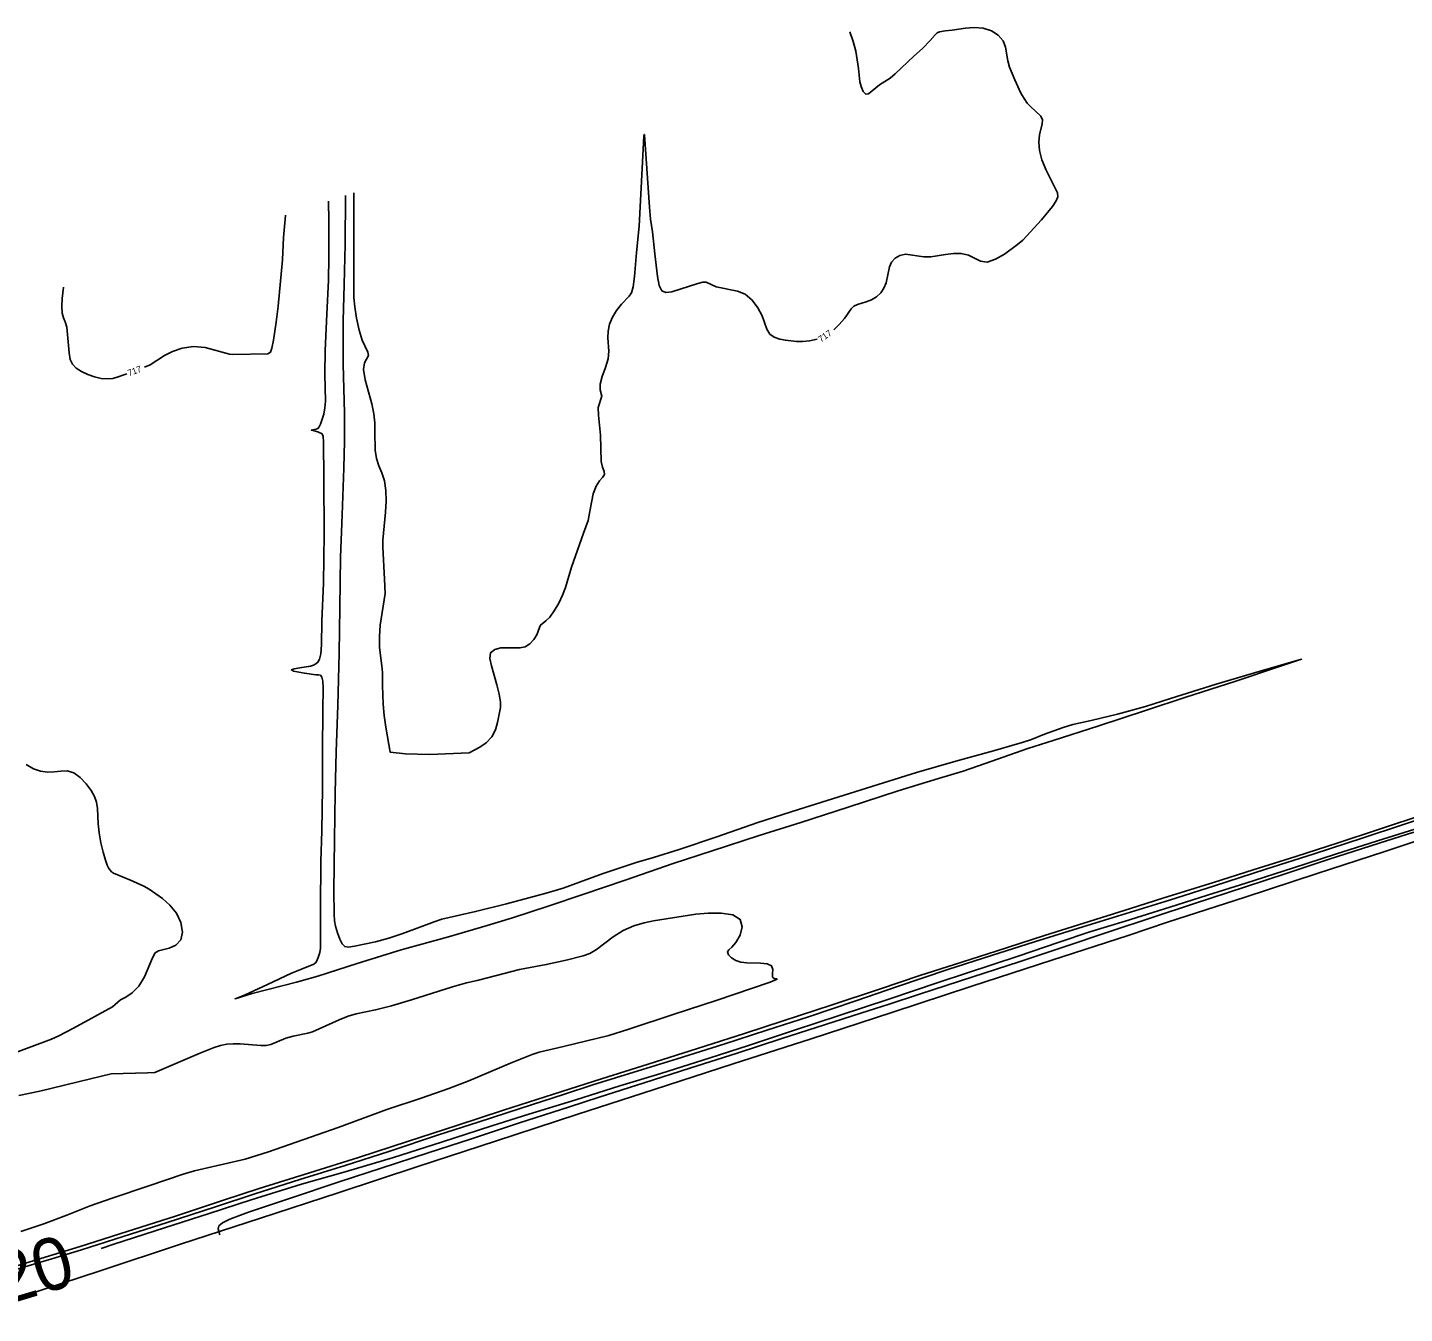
# Model space of a CAD drawing. Extents: x -361782338 to 28259792, y -263199453 to 8342113.
# Drawn here: x 1406946 to 1407815, y 577421 to 578233 of the extents above; entities that cross this region are included whole.
import ezdxf

# ---------------------------------------------------------------- set-up
doc = ezdxf.new("R2010")
doc.units = 0
for name, color, linetype in [('DT_X_Contour_Minor', 7, 'Continuous'), ('Level 14', 7, 'Continuous'), ('Level 19', 7, 'Continuous')]:
    doc.layers.add(name, color=color, linetype=linetype)

msp = doc.modelspace()

# ---------------------------------------------------------------- linework, layer by layer
at = {"layer": 'DT_X_Contour_Minor'}
for points in [[(1407465.01, 578230.1), (1407467.24, 578223.89), (1407468.75, 578217.77), (1407470.43, 578206.82), (1407471.33, 578198.54), (1407472.25, 578195.43), (1407473.56, 578192.44), (1407475.09, 578190.64), (1407476.74, 578190.8), (1407483.85, 578196.54), (1407490.46, 578200.85), (1407493.71, 578203.6), (1407505.45, 578214.64), (1407510.96, 578219.61), (1407515.74, 578224.5), (1407518.82, 578228.2), (1407520.15, 578229.38), (1407521.65, 578230.08), (1407525.14, 578230.58), (1407529.65, 578231.02), (1407537.95, 578232.27), (1407543.52, 578232.76), (1407549.22, 578232.39), (1407554.44, 578230.72), (1407558.77, 578227.92), (1407561.81, 578224.32), (1407563.39, 578220.26), (1407564.68, 578211.72), (1407565.78, 578207.66), (1407569.17, 578199.65), (1407573.04, 578191.42), (1407575.02, 578187.88), (1407577.02, 578185.1), (1407579.09, 578182.89), (1407585.52, 578176.86), (1407586.59, 578174.54), (1407586.47, 578171.89), (1407584.72, 578164.99), (1407584.36, 578160.42), (1407584.84, 578155.12), (1407586.33, 578149.17), (1407588.88, 578142.79), (1407596.04, 578128.33), (1407596.35, 578125.87), (1407595.32, 578123.27), (1407592.95, 578119.78), (1407586.02, 578111.36), (1407574.24, 578098.51), (1407570.86, 578095.77), (1407562.62, 578089.76), (1407557.09, 578086.47), (1407551.82, 578084.64), (1407547.51, 578085.16), (1407539.85, 578089.09), (1407535.35, 578090.07), (1407530.43, 578090.11), (1407525.43, 578089.55), (1407516.13, 578088.06), (1407511.85, 578087.91), (1407500.18, 578089.57), (1407496.64, 578088.83), (1407493.57, 578087.12), (1407491.31, 578084.69), (1407490.07, 578081.74), (1407488.03, 578071.48), (1407486.59, 578068.15), (1407484.52, 578065.18), (1407481.77, 578062.71), (1407478.62, 578060.81), (1407475.41, 578059.48), (1407469.79, 578057.97), (1407467.6, 578056.89), (1407465.83, 578055.04), (1407461.71, 578049.07), (1407458.4, 578045.19), (1407454.89, 578041.92)], [(1407444.39, 578036.01), (1407439.66, 578034.96), (1407435.16, 578034.53), (1407431.32, 578034.49), (1407424.43, 578035.26), (1407420.77, 578036), (1407417.27, 578037.23), (1407414.46, 578039.24), (1407412.68, 578042.25), (1407409.68, 578050.8), (1407407.04, 578055.86), (1407403.44, 578060.64), (1407399.03, 578064.32), (1407394.05, 578066.36), (1407380.71, 578069.08), (1407374.29, 578072.01), (1407372.35, 578071.93), (1407369.14, 578071.07), (1407352.77, 578065.96), (1407348.9, 578065.43), (1407346.39, 578066.52), (1407344.75, 578069.84), (1407343.56, 578075.65), (1407342, 578089.87), (1407340.5, 578103.77), (1407339.31, 578111.73), (1407338.57, 578119.36), (1407336.94, 578143.8), (1407335.49, 578165.04), (1407335.24, 578165.3), (1407335.03, 578164.08), (1407334.03, 578143.7), (1407332.01, 578107.29), (1407330.35, 578090.66), (1407329.05, 578075.48), (1407328.22, 578069.13), (1407327.19, 578065.29), (1407325.76, 578063.04), (1407320.87, 578057.99), (1407317.82, 578054.17), (1407315.17, 578049.89), (1407313.41, 578045.48), (1407312.52, 578041.1), (1407312.35, 578036.84), (1407312.89, 578028.43), (1407312.39, 578023.58), (1407310.78, 578018), (1407308.8, 578012.35), (1407307.45, 578007.49), (1407307.42, 578004.07), (1407308.44, 578000.09), (1407306.14, 577992.87), (1407306.35, 577987.92), (1407307.7, 577975.38), (1407308.02, 577958.64), (1407308.94, 577955.07), (1407309.91, 577952.45), (1407310.11, 577950.46), (1407308.98, 577948.71), (1407306.98, 577946.53), (1407304.83, 577943.19), (1407303.11, 577938.3), (1407301.13, 577928.42), (1407299.81, 577921.59), (1407297.02, 577913.5), (1407289.45, 577892.03), (1407285.59, 577879.14), (1407283.75, 577874.34), (1407281.27, 577869.24), (1407278.43, 577864.4), (1407275.62, 577860.53), (1407273.18, 577858.11), (1407269.88, 577855.43), (1407269.11, 577853.86), (1407267.45, 577849.29), (1407265.62, 577846.4), (1407263.08, 577843.67), (1407260.09, 577841.72), (1407256.82, 577840.98), (1407244.84, 577841.07), (1407240.9, 577840.07), (1407238.32, 577837.93), (1407237.78, 577834.41), (1407238.77, 577829.68), (1407242.31, 577817.82), (1407243.77, 577811.81), (1407244.61, 577806.84), (1407244.63, 577803.44), (1407242.56, 577793.93), (1407241.34, 577789.31), (1407239.09, 577784.82), (1407235.51, 577781.1), (1407231.45, 577778.29), (1407224.81, 577774.81), (1407200, 577773.74), (1407184.66, 577774.24), (1407174.9, 577775.11), (1407172.14, 577790.97), (1407171.14, 577798.37), (1407170.48, 577805.48), (1407170.04, 577817.31)], [(1407135.98, 578123.16), (1407136.07, 578110.73), (1407136.27, 578087.48), (1407136.02, 578073.19), (1407134.99, 578051.77), (1407133.89, 578028.9), (1407133.73, 578013.85), (1407133.98, 577996.9), (1407133.67, 577992.59), (1407132.91, 577988.54), (1407130.89, 577982.22), (1407130.07, 577980.53), (1407129.27, 577979.65), (1407128.25, 577979.24), (1407125.1, 577978.61), (1407126.91, 577978.14), (1407129.21, 577977.43), (1407130.49, 577976.83), (1407131.22, 577976.69), (1407131.95, 577976.13), (1407132.53, 577974.5), (1407132.83, 577971.21), (1407133.04, 577948.18), (1407133.2, 577913.17), (1407132.79, 577881.91), (1407131.67, 577857.9), (1407131.47, 577842.97), (1407131.13, 577837.37), (1407130.36, 577833.87), (1407129.24, 577831.99), (1407127.93, 577830.98), (1407126.47, 577830.24), (1407124.54, 577829.58), (1407117.85, 577828.39), (1407114.25, 577827.78), (1407112.52, 577827.13), (1407113.76, 577826.43), (1407120.71, 577825.08), (1407127.89, 577824.05), (1407129.48, 577824.06), (1407130.81, 577823.77), (1407131.78, 577822.61), (1407132.35, 577820.08), (1407132.59, 577815.87), (1407132.47, 577801.65), (1407132.12, 577776.32), (1407132.13, 577752.26), (1407131.67, 577725.61), (1407131.15, 577706.24), (1407130.89, 577676.89), (1407130.83, 577651.52), (1407130.51, 577648.77), (1407129.45, 577645.46), (1407128.23, 577642.5), (1407126.66, 577641.37), (1407118.83, 577638.14), (1407112.56, 577635.56), (1407097.47, 577628.58), (1407083.37, 577622), (1407076.96, 577619.52), (1407087.68, 577622.76), (1407115.72, 577629.87), (1407129.23, 577633.84), (1407153.96, 577641.72), (1407181.86, 577650.35), (1407211.7, 577658.55), (1407236.15, 577665.78), (1407252, 577670.51), (1407274.62, 577677.95), (1407297.19, 577685.61), (1407323.31, 577694.45), (1407353.45, 577704.82), (1407378.14, 577712.98), (1407407.78, 577722.55), (1407434.11, 577730.86), (1407463.92, 577740.37), (1407495.61, 577750.75), (1407520.96, 577758.48), (1407536.65, 577763.3), (1407550.55, 577768), (1407577.47, 577777.47), (1407593.42, 577782.67), (1407622.22, 577791.82), (1407651.58, 577801.55), (1407677.13, 577809.91), (1407708.01, 577819.89), (1407735.71, 577829.01), (1407750.18, 577833.9), (1407724.02, 577826.3), (1407696.22, 577818.2), (1407667.43, 577809.05), (1407651.68, 577804.14), (1407633.92, 577799.21), (1407617.47, 577795.28), (1407605.83, 577792.7), (1407599.61, 577790.8), (1407587.96, 577786.51), (1407579.67, 577783.17), (1407573.92, 577781.28), (1407555.66, 577776.15), (1407531.88, 577769.53)], [(1407531.88, 577769.53), (1407507.22, 577762.28), (1407486.25, 577755.88), (1407461.55, 577748.04), (1407432.64, 577739.03), (1407406.87, 577730.79), (1407381.17, 577721.76), (1407357.39, 577713.81), (1407341.21, 577708.66), (1407330.24, 577705.6), (1407309.35, 577698.67), (1407294.33, 577693.2), (1407284.04, 577689.32), (1407273.46, 577686.19), (1407248.22, 577679.36), (1407228.81, 577674.58), (1407207.56, 577669.66), (1407202.58, 577668.13), (1407190.25, 577663.48), (1407182.34, 577660.49), (1407173.96, 577657.68), (1407165.71, 577655.46), (1407152.43, 577652.74), (1407148.58, 577652.17), (1407146.21, 577652.48), (1407144.56, 577654.09), (1407143.01, 577657.21), (1407141.58, 577661.2), (1407140.45, 577665.23), (1407139.77, 577668.8), (1407139.44, 577672.9), (1407139.37, 577687.56), (1407139.78, 577720.09), (1407140.18, 577749.51), (1407140.77, 577775.33), (1407141.82, 577804.72), (1407142.66, 577837.74), (1407143.07, 577866.56), (1407143.53, 577898.4), (1407144.5, 577925.04), (1407145.68, 577954.49), (1407146.03, 577971.56), (1407146.03, 577989.3), (1407145.14, 578020.24), (1407145.21, 578047.57), (1407145.87, 578070.46), (1407146.49, 578095.84), (1407146.59, 578126.61)], [(1407170.04, 577817.31), (1407169.97, 577825.48), (1407169.63, 577829.72), (1407168.25, 577841.25), (1407168.05, 577848.17), (1407168.66, 577855.41), (1407171.74, 577875.31), (1407171.41, 577884.43), (1407170.16, 577904.75), (1407170.32, 577909.01), (1407172.03, 577926.72), (1407172.33, 577933.7), (1407172.15, 577940.52), (1407171.28, 577946.59), (1407169.67, 577951.54), (1407167.79, 577955.93), (1407166.22, 577960.55), (1407165.43, 577965.97), (1407165.24, 577977.74), (1407165.16, 577983.22), (1407164.66, 577988.82), (1407163.4, 577995.2), (1407159.2, 578010.37), (1407158.13, 578016.79), (1407158.75, 578021.03), (1407161.18, 578025.59), (1407160.77, 578027.74), (1407157.27, 578035.35), (1407155.34, 578041.76), (1407153.73, 578049.16), (1407152.59, 578056.35), (1407152.04, 578062.34), (1407151.95, 578070.08), (1407152.03, 578080.09), (1407152.04, 578109.63), (1407151.88, 578128.33)], [(1407108.81, 578114.33), (1407108.79, 578114.13), (1407107.47, 578100.11), (1407106.9, 578086.15), (1407104.24, 578056.85), (1407102.99, 578046.73), (1407101.22, 578035.29), (1407100.28, 578030.35), (1407099.34, 578027.68), (1407097.74, 578026.76), (1407075.66, 578026.22), (1407073.39, 578026.47), (1407058.09, 578030.7), (1407050.68, 578031.37), (1407043.62, 578030.36), (1407037.42, 578028.2), (1407032.48, 578025.66), (1407023.31, 578019.78), (1407019.82, 578018.31)], [(1407008.56, 578014.14), (1407006.84, 578013.5), (1407003.26, 578012.14), (1406999.77, 578011.2), (1406996.17, 578010.88), (1406992.37, 578011.19), (1406988.34, 578012.12), (1406984.11, 578013.61), (1406980.09, 578015.54), (1406976.74, 578017.74), (1406974.42, 578020.17), (1406972.99, 578023.22), (1406972.2, 578027.36), (1406970.82, 578043.59), (1406969.79, 578046.95), (1406968.63, 578049.5), (1406967.77, 578052.48), (1406967.53, 578056.73), (1406967.8, 578061.67), (1406968.75, 578068.81)], [(1406931.28, 577582.91), (1406961.05, 577593.95), (1406965.77, 577596.09), (1406975.08, 577600.91), (1406999.61, 577614.3), (1407004.66, 577618.78), (1407007.98, 577620.55), (1407012.13, 577623.2), (1407016.29, 577627.39), (1407019.79, 577633.37), (1407024.79, 577645.31), (1407026.59, 577648.42), (1407028.56, 577649.82), (1407035.37, 577651.51), (1407039.59, 577653.38), (1407042.74, 577656.66), (1407043.8, 577661.64), (1407042.8, 577667.58), (1407040.03, 577673.53), (1407035.9, 577678.66), (1407031.13, 577682.85), (1407022.78, 577688.62), (1407019.35, 577690.6), (1407011.06, 577694.36), (1407000.18, 577698.87), (1406998.9, 577699.68), (1406997.32, 577701.72), (1406996.35, 577703.75), (1406995.14, 577707.1), (1406993.68, 577712.04), (1406992.24, 577718), (1406991.16, 577724.21), (1406990.64, 577730.01), (1406990.21, 577739.73), (1406989.56, 577743.61), (1406988.28, 577747.21), (1406986.14, 577751.02), (1406983.03, 577755.28), (1406979.23, 577759.31), (1406975.12, 577762.2), (1406971.01, 577763.32), (1406966.92, 577763.21), (1406962.8, 577762.71), (1406958.57, 577762.55), (1406954.22, 577763.11), (1406949.7, 577764.67), (1406945.02, 577767.43)], [(1407838.58, 577737.44), (1407813.86, 577729.31), (1407788.46, 577720.85), (1407758.17, 577710.96), (1407727.68, 577701.27), (1407695.22, 577690.89), (1407666.84, 577681.75), (1407636.78, 577672.52), (1407612.1, 577664.91), (1407581.56, 577655.39), (1407554.55, 577646.85), (1407526.81, 577638.06), (1407495.18, 577627.19), (1407468.88, 577618.21), (1407439.01, 577608.18), (1407412.68, 577599.56), (1407385.54, 577590.77), (1407355.99, 577581.56), (1407331.51, 577573.94), (1407302.89, 577565.1), (1407284.89, 577559.34), (1407256.89, 577550.18), (1407230.48, 577541.63), (1407205.49, 577533.48), (1407174.14, 577523.14), (1407146.51, 577514.27), (1407117.89, 577505.31), (1407089.38, 577496.26), (1407064.62, 577488.19), (1407034.13, 577478.27), (1407006.29, 577469.48), (1406979.95, 577461.05), (1406961.37, 577455.32), (1406935.08, 577447.53)], [(1407642.25, 577676.49), (1407662.7, 577682.97), (1407694.65, 577692.99), (1407719.69, 577700.97), (1407746.53, 577709.42), (1407773.37, 577718.01), (1407798.78, 577726.34), (1407828.57, 577736.31)], [(1406992.43, 577461.87), (1407000.49, 577464.47), (1407032.36, 577474.87), (1407060.68, 577483.93), (1407087.17, 577492.48), (1407118.95, 577502.52), (1407146.43, 577510.28), (1407177.01, 577519.27), (1407207.26, 577528.98), (1407239.07, 577539.31), (1407262.39, 577546.62), (1407292, 577555.77), (1407319.92, 577564.45), (1407345.79, 577572.37), (1407376.87, 577582.18), (1407401.02, 577590.05), (1407430.21, 577599.69), (1407458.22, 577608.85), (1407489.57, 577619.21), (1407520.72, 577629.71), (1407538.64, 577635.6), (1407571.25, 577646.32), (1407596.47, 577655.07), (1407616.56, 577661.84), (1407638.8, 577668.56), (1407666.96, 577677.38), (1407690.77, 577685), (1407715, 577692.59), (1407745.18, 577702.27), (1407771.54, 577710.88), (1407798.17, 577719.31), (1407828.49, 577728.79)], [(1407067.35, 577470.36), (1407066.32, 577474.21), (1407066.8, 577476.03), (1407069.06, 577478.04), (1407073.62, 577480.32), (1407085.48, 577484.76), (1407110.73, 577493.25), (1407143.34, 577504.1), (1407169.13, 577512.54), (1407198.83, 577522.14), (1407226.12, 577531.05), (1407256.6, 577541.05), (1407287.43, 577551.11), (1407306.91, 577557.43), (1407335.12, 577566.44), (1407364.1, 577575.67), (1407393.86, 577585.16), (1407421.43, 577594.11), (1407449.75, 577603.26), (1407472.04, 577610.41), (1407489.83, 577616.11), (1407508.92, 577622.33), (1407542.62, 577633.32), (1407571.92, 577642.9), (1407598.41, 577651.65), (1407629.22, 577662.02), (1407655.8, 577670.8), (1407682.05, 577679.49), (1407714.78, 577690.23), (1407740.39, 577698.63), (1407767.08, 577707.37), (1407799.09, 577717.64), (1407821.06, 577724.66)], [(1406927.48, 577447.25), (1406949.59, 577454.07), (1406979.13, 577463.13), (1407008.89, 577472.53), (1407039.47, 577482.15), (1407069.77, 577492.36), (1407092.17, 577499.63), (1407123.91, 577509.61), (1407154.96, 577519.29), (1407186.51, 577529.53), (1407216.91, 577539.53), (1407246.52, 577549.05), (1407277.91, 577559.24), (1407308.27, 577568.95), (1407337.77, 577578.3), (1407368.79, 577588.08), (1407398.5, 577597.61), (1407423.03, 577605.54), (1407453.82, 577615.69), (1407483.68, 577625.45), (1407509.33, 577634.18), (1407531.05, 577641.22), (1407557.35, 577649.58), (1407587.92, 577659.45), (1407612.72, 577667.26), (1407642.25, 577676.49)], [(1406941.72, 577472.51), (1406956.23, 577477.33), (1406970.78, 577482.86), (1406985.55, 577488.78), (1406999.46, 577493.61), (1407022.56, 577501.45), (1407044.16, 577508.8), (1407051.39, 577510.8), (1407083.39, 577518.27), (1407098.02, 577522.91), (1407128.74, 577533.64), (1407142.08, 577538.2), (1407172.74, 577549.58), (1407194.38, 577556.82), (1407211.86, 577562.81), (1407224.45, 577567.73), (1407250.86, 577578.79), (1407264.6, 577584.36), (1407268.91, 577585.73), (1407284.39, 577589.42), (1407312.93, 577596.33), (1407325.59, 577600.3), (1407354.23, 577609.74), (1407380.74, 577618.48), (1407414.85, 577629.95), (1407419.15, 577631.79), (1407418.77, 577632.02), (1407417.35, 577632.26), (1407416.2, 577633.22), (1407416.19, 577635.35), (1407416.44, 577638.03), (1407415.64, 577640.33), (1407412.87, 577641.58), (1407408.71, 577642.02), (1407399.97, 577642.22), (1407396.31, 577642.67), (1407393.11, 577643.66), (1407390.39, 577645.31), (1407388.49, 577647.26), (1407387.79, 577649.04), (1407388.57, 577650.4), (1407390.49, 577652.05), (1407393.08, 577654.93), (1407395.72, 577659.58), (1407397.13, 577664.95), (1407395.91, 577669.61), (1407391.11, 577672.43), (1407383.82, 577673.59), (1407375.6, 577673.57), (1407367.8, 577672.83), (1407341.21, 577668.63), (1407335.3, 577667.42), (1407328.67, 577665.48), (1407321.95, 577662.57), (1407315.7, 577658.6), (1407305.15, 577650.58), (1407300.84, 577648.11), (1407296.62, 577646.54), (1407285.94, 577643.85), (1407273.43, 577641.1), (1407256.47, 577638), (1407241.14, 577633.87), (1407229.81, 577630.93), (1407223.1, 577629.53), (1407214.14, 577626.95), (1407188.37, 577618.91), (1407175.68, 577615.03), (1407165.73, 577612.48), (1407153.36, 577610.06), (1407148.46, 577608.57), (1407142.76, 577606.29), (1407125.96, 577598.65), (1407122.83, 577597.82), (1407113.57, 577595.86), (1407108.93, 577594.58), (1407099.56, 577590.52), (1407096.58, 577590.04), (1407093.2, 577590.05), (1407080.28, 577590.99), (1407075.8, 577591.05), (1407071.72, 577590.73), (1407067.84, 577589.99), (1407063.8, 577588.76), (1407054.37, 577584.93), (1407026.43, 577572.9), (1407021.66, 577572.7), (1406998.67, 577572), (1406985.64, 577568.87), (1406953.79, 577561.24), (1406940.48, 577558.31)]]:
    msp.add_lwpolyline(points, dxfattribs=at)
at = {"layer": 'Level 14'}
for points in [[(1407851.62, 577728.65), (1407802.75, 577712.58), (1407759.96, 577698.61), (1407714.49, 577683.55), (1407665.6, 577667.78), (1407640.75, 577659.49), (1407592.64, 577643.89), (1407542.13, 577627.36), (1407491.56, 577610.88), (1407440.72, 577594.29), (1407391.45, 577578.32), (1407341.58, 577562.1), (1407292.71, 577546.44), (1407242.09, 577529.8), (1407192.41, 577513.54), (1407141.96, 577496.91), (1407093.05, 577480.86), (1407042.52, 577464.45)], [(1407042.52, 577464.45), (1406991.9, 577447.79), (1406942.94, 577431.72)]]:
    msp.add_lwpolyline(points, dxfattribs=at)

# ---------------------------------------------------------------- texts
at = {"layer": 'Level 19'}
for s, height, rotation, p in [('717', 4, 34.28579, (1407446.78, 578033.82)), ('717', 4, 20.26552, (1407009.95, 578012.52)), ('720', 33, 16.76474, (1406907.41, 577418.51))]:
    msp.add_text(s, height=height, rotation=rotation, dxfattribs=at).set_placement(p)

doc.saveas('drawing.dxf')
